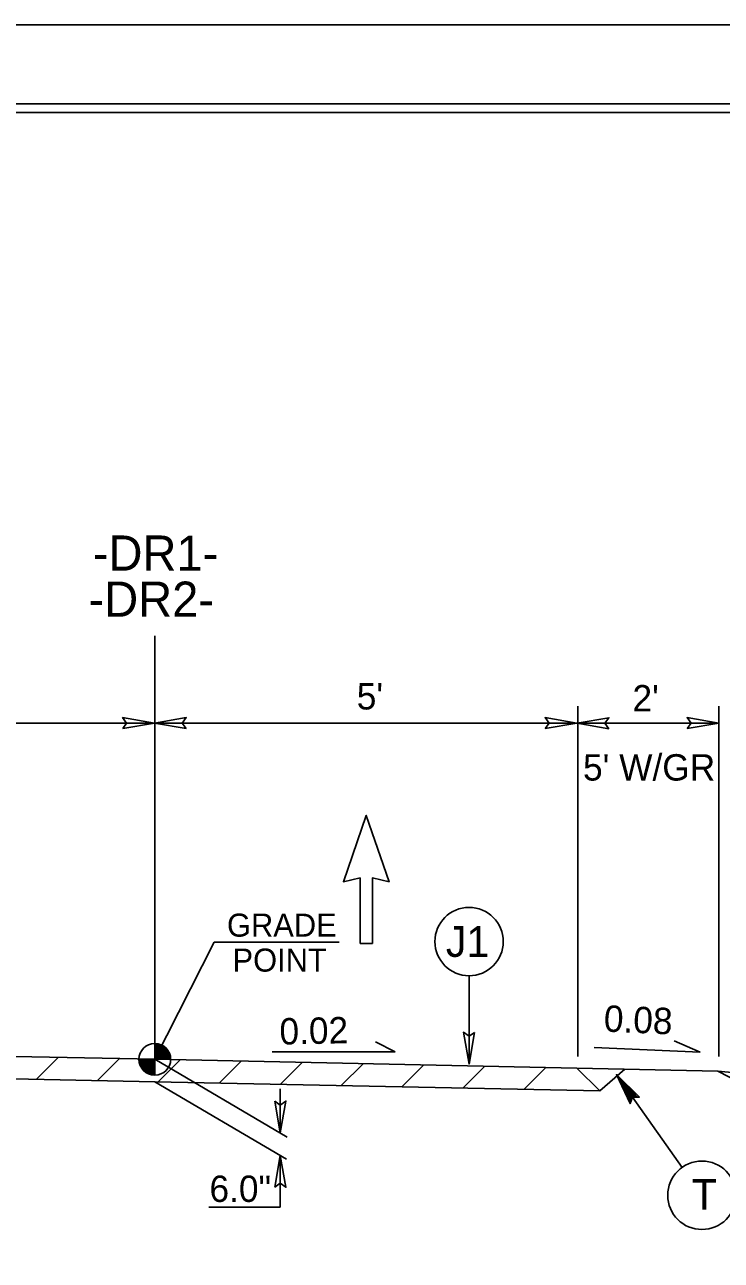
# Model space of a CAD drawing. Extents: x 1542177 to 1542464, y 45134 to 45344.
# Drawn here: x 1542299.26 to 1542315.1, y 45194.34 to 45222.45 of the extents above; entities that cross this region are included whole.
import ezdxf

# ---------------------------------------------------------------- set-up
doc = ezdxf.new("R2010")
doc.units = 0
for name, color, linetype in [('Default', 7, 'Continuous'), ('Old_Level_11', 7, 'Continuous'), ('Old_Level_3', 7, 'Continuous'), ('Sheet Cutting Line CELL', 7, 'Continuous'), ('Sheet Plot Border Inside CELL', 7, 'Continuous'), ('Sheet Plot Border Outside CELL', 7, 'Continuous'), ('Sheet Typical CELL', 7, 'Continuous'), ('Typical Detail Wedge3 CELL', 7, 'Continuous'), ('Typical ID Circle CELL', 7, 'Continuous'), ('Typical Text ID Circle CELL', 7, 'Continuous')]:
    doc.layers.add(name, color=color, linetype=linetype)

# ---------------------------------------------------------------- blocks, each defined once
blk = doc.blocks.new('GP_1')
at = {"layer": 'Default'}
blk.add_line((-0.001, -0.343), (0, 0), dxfattribs=at)
for points in [[(0.342, 0), (0.343, 0), (0, 0), (0, 0.343), (0, 0.343)], [(0.003, 0.343), (0.003, 0.343), (0.003, 0)], [(0.01, 0.343), (0.01, 0)], [(0.017, 0.342), (0.017, 0)], [(0.024, 0.342), (0.024, 0)], [(0.03, 0.341), (0.03, 0)], [(0.037, 0.341), (0.037, 0)], [(0.044, 0.34), (0.044, 0)], [(0.051, 0.339), (0.051, 0)], [(0.058, 0.338), (0.058, 0)], [(0.065, 0.337), (0.065, 0)], [(0.072, 0.335), (0.072, 0)], [(0.079, 0.334), (0.079, 0)], [(0.085, 0.332), (0.085, 0)], [(0.092, 0.33), (0.092, 0)], [(0.099, 0.328), (0.099, 0)], [(0.106, 0.326), (0.106, 0)], [(0.113, 0.324), (0.113, 0)], [(0.12, 0.321), (0.12, 0)], [(0.126, 0.319), (0.126, 0)], [(0.133, 0.316), (0.133, 0)], [(0.14, 0.312), (0.14, 0)], [(0.147, 0.309), (0.147, 0)], [(0.154, 0.306), (0.154, 0)], [(0.161, 0.302), (0.161, 0)], [(0.168, 0.299), (0.168, 0)], [(0.175, 0.295), (0.175, 0)], [(0.181, 0.291), (0.181, 0)], [(0.188, 0.286), (0.188, 0)], [(0.195, 0.282), (0.195, 0)], [(0.202, 0.277), (0.202, 0)], [(0.209, 0.272), (0.209, 0)], [(-0.343, 0), (0, 0), (-0.001, -0.343), (-0.001, -0.343)], [(-0.343, 0), (-0.343, 0)], [(-0.341, 0), (-0.341, -0.037)], [(-0.335, 0), (-0.335, -0.078)], [(-0.328, 0), (-0.328, -0.102)], [(-0.321, 0), (-0.321, -0.123)], [(-0.314, 0), (-0.314, -0.139)], [(-0.307, 0), (-0.307, -0.153)], [(-0.3, 0), (-0.3, -0.166)], [(-0.293, 0), (-0.293, -0.178)], [(-0.286, 0), (-0.286, -0.189)], [(-0.28, 0), (-0.28, -0.199)], [(-0.273, 0), (-0.273, -0.208)], [(-0.266, 0), (-0.266, -0.216)], [(-0.259, 0), (-0.259, -0.225)], [(-0.252, 0), (-0.252, -0.232)], [(-0.245, 0), (-0.245, -0.24)], [(-0.238, 0), (-0.238, -0.247)], [(-0.232, 0), (-0.232, -0.253)], [(-0.225, 0), (-0.225, -0.259)], [(-0.218, 0), (-0.218, -0.265)], [(-0.211, 0), (-0.211, -0.271)], [(-0.204, 0), (-0.204, -0.276)], [(-0.197, 0), (-0.197, -0.281)], [(-0.191, 0), (-0.191, -0.285)], [(-0.184, 0), (-0.184, -0.29)], [(-0.177, 0), (-0.177, -0.294)], [(-0.17, 0), (-0.17, -0.298)], [(-0.163, 0), (-0.163, -0.302)], [(-0.156, 0), (-0.156, -0.306)], [(-0.149, 0), (-0.149, -0.309)], [(-0.142, 0), (-0.142, -0.312)], [(-0.135, 0), (-0.135, -0.315)], [(-0.129, 0), (-0.129, -0.318)], [(-0.122, 0), (-0.122, -0.321)], [(-0.115, 0), (-0.115, -0.323)], [(-0.108, 0), (-0.108, -0.325)], [(-0.101, 0), (-0.101, -0.328)], [(-0.095, 0), (-0.095, -0.329)], [(-0.088, 0), (-0.088, -0.331)], [(-0.081, 0), (-0.081, -0.333)], [(-0.074, 0), (-0.074, -0.335)], [(-0.067, 0), (-0.067, -0.336)], [(-0.06, 0), (-0.06, -0.338)], [(-0.053, 0), (-0.053, -0.338)], [(-0.046, 0), (-0.046, -0.34)], [(-0.04, 0), (-0.04, -0.341)], [(-0.033, 0), (-0.033, -0.341)], [(-0.026, 0), (-0.026, -0.342)], [(-0.019, 0), (-0.019, -0.342)], [(-0.012, 0), (-0.012, -0.343)], [(-0.005, 0), (-0.005, -0.343), (-0.005, -0.343)], [(0.216, 0.267), (0.216, 0)], [(0.223, 0.261), (0.223, 0)], [(0.229, 0.255), (0.229, 0)], [(0.236, 0.248), (0.236, 0)], [(0.243, 0.241), (0.243, 0)], [(0.25, 0.235), (0.25, 0)], [(0.257, 0.227), (0.257, 0)], [(0.264, 0.219), (0.264, 0)], [(0.271, 0.21), (0.271, 0)], [(0.277, 0.201), (0.277, 0)], [(0.284, 0.191), (0.284, 0)], [(0.291, 0.18), (0.291, 0)], [(0.298, 0.169), (0.298, 0)], [(0.305, 0.157), (0.305, 0)], [(0.312, 0.142), (0.312, 0)], [(0.319, 0.126), (0.319, 0)], [(0.326, 0.107), (0.326, 0)], [(0.332, 0.084), (0.332, 0)], [(0.339, 0.049), (0.339, 0)]]:
    blk.add_lwpolyline(points, dxfattribs=at)
blk.add_circle((0, 0), 0.343, dxfattribs=at)
for start, end in [(359.9905, 89.9905), (179.9905, 269.9905)]:
    blk.add_arc((0, 0), 0.343, start, end, dxfattribs=at)
blk = doc.blocks.new('ARROW3_1')
at = {"layer": 'Default'}
blk.add_lwpolyline([(-0.0267, -0.5547), (-0.0267, -0.2704), (-0.0991, -0.2874), (0, 0), (0.099, -0.2874), (0.0267, -0.2704), (0.0267, -0.5547), (-0.0267, -0.5547)], dxfattribs=at)
blk = doc.blocks.new('CIR')
at = {"layer": 'Default'}
blk.add_line((0, 1.914), (0, 0), dxfattribs=at)
blk.add_lwpolyline([(0.118, 0.686), (0, 0), (-0.122, 0.69), (0, 0.602)], close=True, dxfattribs=at)
blk.add_circle((0, 2.654), 0.741, dxfattribs=at)

msp = doc.modelspace()

# ---------------------------------------------------------------- linework, layer by layer
at = {"layer": 'Default'}
for p, q in [((1542302.22, 45198.914), (1542302.22, 45208.549)), ((1542302.22, 45198.914), (1542302.22, 45208.549)), ((1542311.84, 45198.982), (1542311.84, 45206.949)), ((1542315.048, 45198.982), (1542315.048, 45206.949)), ((1542292.62, 45206.56), (1542302.22, 45206.56)), ((1542292.62, 45206.56), (1542302.22, 45206.56)), ((1542302.22, 45206.56), (1542311.82, 45206.56)), ((1542302.22, 45206.56), (1542311.82, 45206.56)), ((1542311.82, 45206.56), (1542315.048, 45206.56)), ((1542302.22, 45198.914), (1542303.568, 45201.578)), ((1542302.22, 45198.914), (1542303.568, 45201.578)), ((1542307.688, 45199.084), (1542307.235, 45199.311)), ((1542307.688, 45199.084), (1542307.235, 45199.311)), ((1542312.214, 45199.184), (1542314.62, 45199.078)), ((1542314.62, 45199.078), (1542314.034, 45199.337)), ((1542302.22, 45198.914), (1542292.619, 45199.114)), ((1542299.529, 45198.46), (1542300.028, 45198.96)), ((1542300.914, 45198.432), (1542301.413, 45198.931)), ((1542311.821, 45198.714), (1542302.22, 45198.914)), ((1542305.23, 45197.147), (1542302.22, 45198.914)), ((1542302.299, 45198.403), (1542302.798, 45198.902)), ((1542303.685, 45198.374), (1542304.184, 45198.873)), ((1542304.888, 45199.084), (1542307.688, 45199.084)), ((1542304.888, 45199.084), (1542307.688, 45199.084)), ((1542292.099, 45198.615), (1542302.22, 45198.404)), ((1542305.07, 45198.345), (1542305.569, 45198.844)), ((1542306.459, 45198.319), (1542306.955, 45198.815)), ((1542307.841, 45198.287), (1542308.34, 45198.786)), ((1542309.226, 45198.259), (1542309.725, 45198.757)), ((1542310.612, 45198.23), (1542311.111, 45198.729)), ((1542311.82, 45198.714), (1542315.021, 45198.647)), ((1542312.34, 45198.194), (1542311.821, 45198.713)), ((1542312.34, 45198.194), (1542312.912, 45198.691)), ((1542315.021, 45198.647), (1542322.468, 45194.788)), ((1542315.021, 45198.647), (1542322.44, 45197.886)), ((1542302.22, 45198.404), (1542312.34, 45198.194)), ((1542305.217, 45196.645), (1542302.22, 45198.404)), ((1542305.074, 45197.239), (1542305.074, 45198.244)), ((1542305.074, 45195.551), (1542305.074, 45196.729)), ((1542303.451, 45195.551), (1542305.074, 45195.551))]:
    msp.add_line(p, q, dxfattribs=at)
for points in [[(1542301.489, 45206.437), (1542302.209, 45206.561), (1542301.485, 45206.689), (1542301.577, 45206.561)], [(1542301.489, 45206.437), (1542302.209, 45206.561), (1542301.485, 45206.689), (1542301.577, 45206.561)], [(1542302.929, 45206.437), (1542302.209, 45206.561), (1542302.933, 45206.689), (1542302.841, 45206.561)], [(1542302.929, 45206.437), (1542302.209, 45206.561), (1542302.933, 45206.689), (1542302.841, 45206.561)], [(1542311.1, 45206.436), (1542311.82, 45206.56), (1542311.096, 45206.688), (1542311.188, 45206.56)], [(1542311.1, 45206.436), (1542311.82, 45206.56), (1542311.096, 45206.688), (1542311.188, 45206.56)], [(1542312.542, 45206.433), (1542311.822, 45206.557), (1542312.546, 45206.685), (1542312.454, 45206.557)], [(1542312.542, 45206.433), (1542311.822, 45206.557), (1542312.546, 45206.685), (1542312.454, 45206.557)], [(1542314.328, 45206.436), (1542315.048, 45206.56), (1542314.324, 45206.688), (1542314.416, 45206.56)], [(1542304.95, 45197.959), (1542305.074, 45197.239), (1542305.202, 45197.963), (1542305.074, 45197.871)], [(1542304.95, 45196.009), (1542305.074, 45196.729), (1542305.202, 45196.005), (1542305.074, 45196.097)]]:
    msp.add_lwpolyline(points, close=True, dxfattribs=at)
at = {"layer": 'Old_Level_3'}
msp.add_line((1542303.568, 45201.578), (1542306.413, 45201.578), dxfattribs=at)
at = {"layer": 'Sheet Cutting Line CELL'}
msp.add_line((1542360.727, 45222.448), (1542226.007, 45222.448), dxfattribs=at)
at = {"layer": 'Sheet Plot Border Inside CELL'}
msp.add_lwpolyline([(1542360.367, 45220.652), (1542227.047, 45220.652), (1542227.047, 45136.244), (1542360.367, 45136.244)], close=True, dxfattribs=at)
at = {"layer": 'Sheet Plot Border Outside CELL'}
msp.add_lwpolyline([(1542360.727, 45222.448), (1542226.007, 45222.448), (1542226.007, 45134.448), (1542360.727, 45134.448)], close=True, dxfattribs=at)
at = {"layer": 'Sheet Typical CELL'}
msp.add_lwpolyline([(1542359.367, 45220.448), (1542239.367, 45220.448), (1542239.367, 45136.448), (1542359.367, 45136.448)], close=True, dxfattribs=at)
at = {"layer": 'Typical Detail Wedge3 CELL'}
msp.add_lwpolyline([(1542313.03, 45197.908), (1542313.08, 45198.057), (1542313.239, 45198.056), (1542312.718, 45198.568), (1542313.194, 45198.056), (1542313.148, 45198.058), (1542312.718, 45198.568), (1542313.104, 45198.058), (1542313.08, 45198.057), (1542312.718, 45198.568), (1542313.067, 45198.016), (1542313.053, 45197.973), (1542312.718, 45198.568), (1542313.038, 45197.93), (1542313.03, 45197.908), (1542312.718, 45198.568)], dxfattribs=at)
at = {"layer": 'Typical ID Circle CELL'}
msp.add_line((1542314.213, 45196.456), (1542313.08, 45198.057), dxfattribs=at)
msp.add_circle((1542314.662, 45195.821), 0.778, dxfattribs=at)

# ---------------------------------------------------------------- block references
at = {"layer": 'Default'}
for name, p, xscale, yscale in [('ARROW3_1', (1542307.028, 45204.461), 5.249333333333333, 5.249333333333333), ('CIR', (1542309.367, 45198.807), 1.0498642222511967, 1.0498642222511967), ('GP_1', (1542302.22, 45198.914), 1.0498642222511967, 1.0498642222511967)]:
    msp.add_blockref(name, p, dxfattribs=dict(at, xscale=xscale, yscale=yscale))

# ---------------------------------------------------------------- texts
for s, height, rotation, p in [('-DR1-', 0.8, 359.9469, (1542300.81, 45210.031)), ('-DR2-', 0.8, 359.9469, (1542300.713, 45208.983)), ('0.08', 0.6, 357.4846, (1542312.421, 45199.547)), ('0.02', 0.6, 1.1916, (1542305.061, 45199.248))]:
    msp.add_text(s, height=height, rotation=rotation, dxfattribs=at).set_placement(p)
for s, height, p in [("5'", 0.6, (1542306.812, 45206.872)), ("2'", 0.6, (1542313.083, 45206.828)), ("5' W/GR", 0.6, (1542311.958, 45205.255)), ('J1', 0.6982, (1542308.839, 45201.245)), ('6.0"', 0.6, (1542303.463, 45195.67))]:
    msp.add_text(s, height=height, dxfattribs=at).set_placement(p)
at = {"layer": 'Old_Level_11'}
for s, p in [('GRADE', (1542303.861, 45201.704)), ('POINT', (1542303.987, 45200.909))]:
    msp.add_text(s, height=0.5248, dxfattribs=at).set_placement(p)
at = {"layer": 'Typical Text ID Circle CELL'}
msp.add_text('T', height=0.696, dxfattribs=at).set_placement((1542314.434, 45195.493))

doc.saveas('drawing.dxf')
